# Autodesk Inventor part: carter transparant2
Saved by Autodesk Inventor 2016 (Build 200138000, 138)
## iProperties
Created: 2013-10
Part Number: carter transparant2
Material: Générique
Document SubType Name: Modeling
Designer: Bruno
Density: 1 g/cm^3
Appearance: Par défaut
Author: Bruno
Sending System: SolidWorks 2013
Last Author: christophe
Last Saved: 2014-02-15
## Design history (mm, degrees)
feature "Enlèv. mat.-Extru.30"
node "Solide1"
